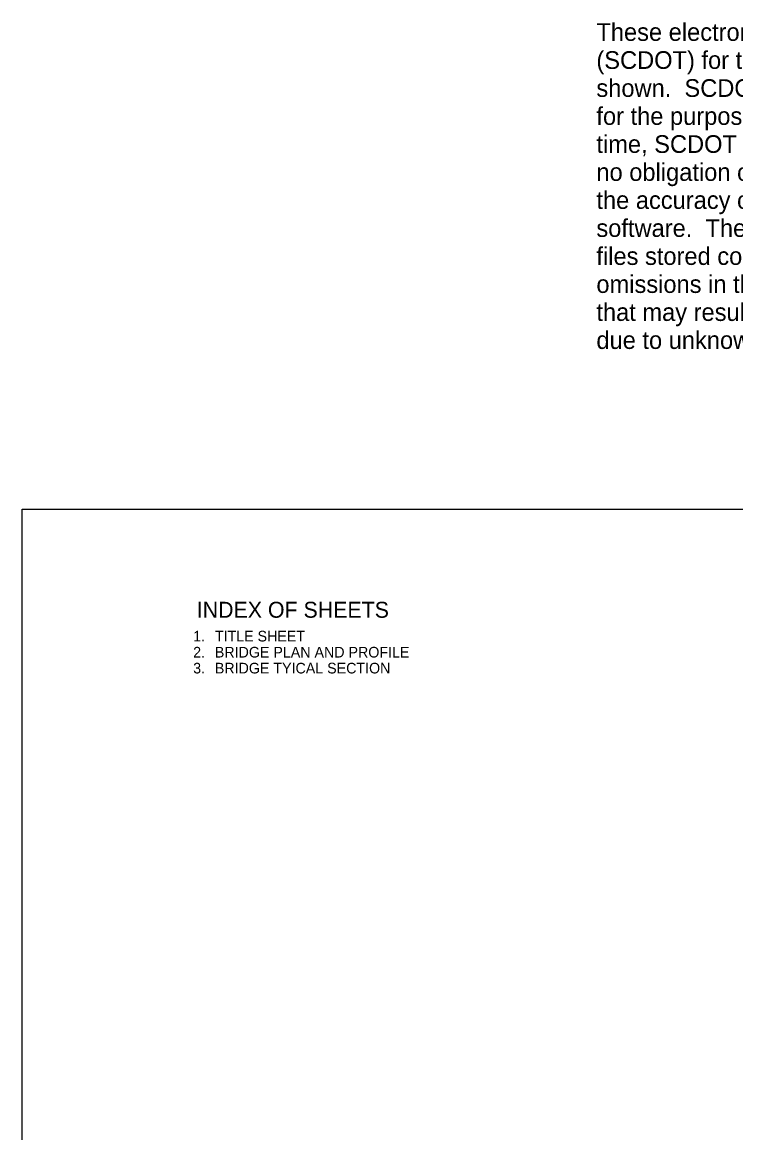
# Model space of a CAD drawing. Extents: x -2.83 to 3.9, y -2.5 to 2.32.
# Drawn here: x 0.167 to 0.865, y 1.182 to 2.268 of the extents above; entities that cross this region are included whole.
import ezdxf

# ---------------------------------------------------------------- set-up
doc = ezdxf.new("R2010")
doc.units = 0
for name, color, linetype in [('BR_BORDER LINES', 7, 'Continuous'), ('BR_USER NOTES', 7, 'Continuous'), ('Default', 7, 'Continuous')]:
    doc.layers.add(name, color=color, linetype=linetype)

msp = doc.modelspace()

# ---------------------------------------------------------------- linework, layer by layer
at = {"layer": 'BR_BORDER LINES'}
msp.add_lwpolyline([(0.1667, 1.7917), (2.7917, 1.7917), (2.7917, 0.0417), (0.1667, 0.0417)], close=True, dxfattribs=at)

# ---------------------------------------------------------------- texts
at = {"layer": 'BR_USER NOTES'}
for s, height, p in [('These electronic files were created by the South Carolina Department of Transportation', 0.017305, (0.7286, 2.2499)), ('(SCDOT) for the sole purpose of creating a set of plans for project development at the site', 0.017305, (0.7286, 2.2225)), ('shown.  SCDOT believes that the information contained herein is reliable and generally accurate', 0.017305, (0.7286, 2.1951)), ('for the purpose intended.  However, since physical conditions may vary and can change over', 0.017305, (0.7286, 2.1677)), ('time, SCDOT makes no performance guarantees, express or implied warranties and assumes', 0.017305, (0.7286, 2.1403)), ('no obligation or liability for the reliability or accuracy of the information contained herein: or for', 0.0173049, (0.7286, 2.1129)), ("the accuracy of the information translated by the Department's software for use with end user's", 0.017305, (0.7286, 2.0855)), ('software.  The paper copy of the electronic information provided shall govern over the electronic', 0.017305, (0.7286, 2.0581)), ('files stored copy.  Only the paper copy of the information may be used to determine errors and', 0.017305, (0.7286, 2.0307)), ('omissions in the bid documents.  SCDOT assumes no liability for hardware or software damage', 0.017305, (0.7286, 2.0033)), ('that may result from the use of the electronic files provided on disk, tape or by electronic transfer', 0.0173049, (0.7286, 1.9759)), ('due to unknown viruses that may reside on the electronic media when transferred to the end user.', 0.017305, (0.7286, 1.9485))]:
    msp.add_text(s, height=height, rotation=360, dxfattribs=at).set_placement(p)
at = {"layer": 'Default'}
for s, height, p in [('INDEX OF SHEETS', 0.015625, (0.3375, 1.6855)), ('1.', 0.01042, (0.334, 1.6623)), ('TITLE SHEET', 0.010417, (0.3552, 1.6623)), ('2.', 0.01042, (0.334, 1.6466)), ('BRIDGE PLAN AND PROFILE', 0.010417, (0.3552, 1.6466)), ('3.', 0.01042, (0.334, 1.631)), ('BRIDGE TYICAL SECTION', 0.010417, (0.3552, 1.631))]:
    msp.add_text(s, height=height, dxfattribs=at).set_placement(p)

doc.saveas('drawing.dxf')
